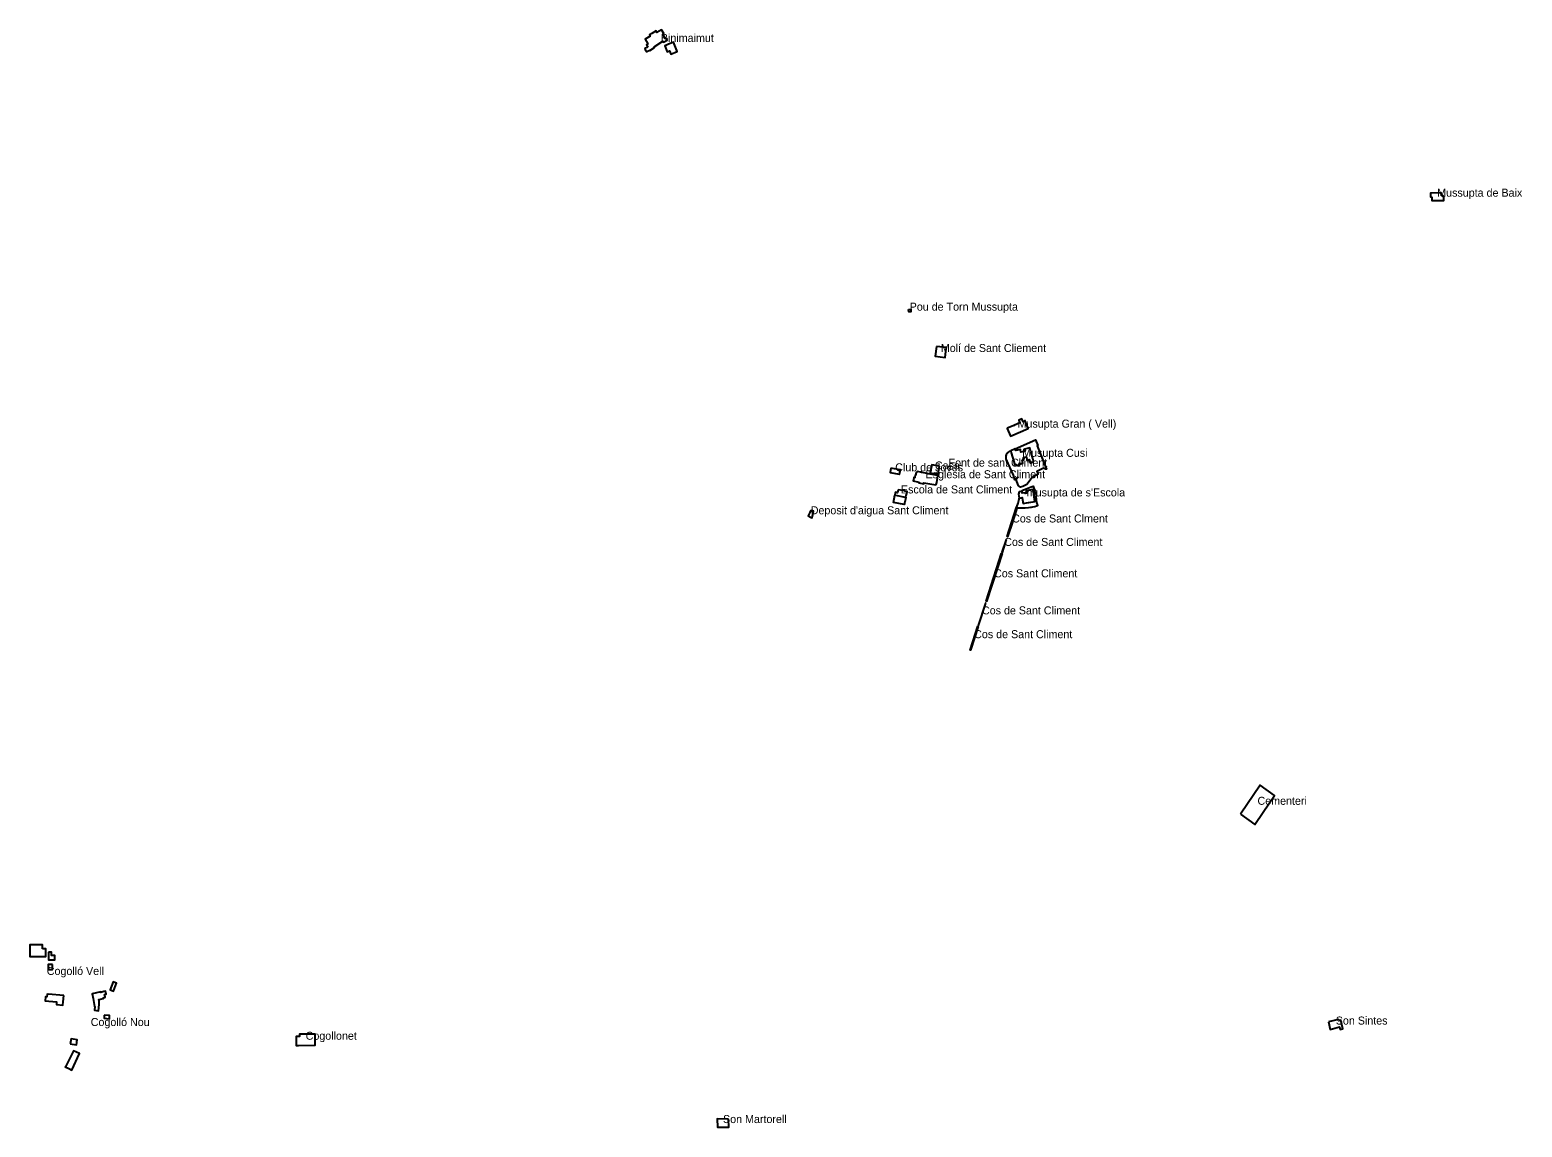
# Model space of a CAD drawing. Extents: x 599451 to 612034, y 4411179 to 4428219.
# Drawn here: x 601945 to 604183, y 4413252 to 4414898 of the extents above; entities that cross this region are included whole.
import ezdxf

# ---------------------------------------------------------------- set-up
doc = ezdxf.new("R2010")
doc.units = 0
for name, color, linetype in [('1', 7, 'Continuous'), ('Bé Arquitectònic', 7, 'Continuous'), ('Elememnts patrimonials', 7, 'Continuous'), ('Elements patrimonials', 7, 'Continuous')]:
    doc.layers.add(name, color=color, linetype=linetype)

msp = doc.modelspace()

# ---------------------------------------------------------------- linework, layer by layer
at = {"layer": '1'}
for points in [[(603262.3, 4414478.5), (603265.8, 4414478.8), (603266.1, 4414475.1), (603262.7, 4414474.8)], [(603322, 4414243.2), (603323.1, 4414243), (603323, 4414242.3), (603321.9, 4414242.5)], [(603424.1, 4414180.3), (603425.1, 4414180.5), (603422.4, 4414172.1), (603418.5, 4414160.1), (603418.3, 4414159.4), (603411.1, 4414137.6), (603410.5, 4414137.8)], [(603409.5, 4414133.3), (603408.8, 4414133.5), (603402.6, 4414114.3), (603403.2, 4414114.1)], [(603402.1, 4414112.8), (603402.7, 4414112.6), (603396.3, 4414092.7), (603379.4, 4414040.6), (603378.7, 4414040.8)], [(603378.4, 4414037.7), (603377.8, 4414037.9), (603366.8, 4414004.6), (603367.5, 4414004.3)], [(603366.4, 4414003.3), (603367.1, 4414003.1), (603355.4, 4413967.6), (603354.7, 4413967.4)]]:
    msp.add_lwpolyline(points, close=True, dxfattribs=at)
at = {"layer": 'Bé Arquitectònic'}
for points in [[(602871.5, 4414872.3), (602866.9, 4414869.9), (602866.8, 4414869.8), (602867.3, 4414868.8), (602868.7, 4414866.2), (602868.9, 4414865.8), (602869.3, 4414865), (602870, 4414865.4), (602874.4, 4414867.7), (602874.7, 4414867.3), (602881.5, 4414871.6), (602880.8, 4414872.7), (602894.1, 4414881.1), (602895.2, 4414879.4), (602900.6, 4414882.7), (602900.3, 4414883.5), (602899.6, 4414885.3), (602898.2, 4414884.5), (602894.1, 4414891.9), (602895.3, 4414892.5), (602892.2, 4414898.2), (602885.2, 4414894.3), (602884, 4414896.2), (602883.8, 4414896.6), (602877.7, 4414892.8), (602874.2, 4414890.5), (602875.2, 4414888.6), (602867.3, 4414884.3), (602871.6, 4414876.9), (602869.4, 4414875.6)], [(602900.7, 4414875.7), (602896.9, 4414874.2), (602900.4, 4414865.3), (602904.2, 4414866.7), (602906.1, 4414861.8), (602915.5, 4414865.5), (602914.8, 4414867.3), (602910.1, 4414879.4), (602901.6, 4414876.1)], [(604061.5, 4414649.2), (604061.3, 4414653.7), (604046.3, 4414653.2), (604045.4, 4414653.1), (604045.3, 4414647.4), (604047.4, 4414647.3), (604047.2, 4414641.9), (604061.2, 4414642.2), (604061.9, 4414642.2), (604065.3, 4414641.9), (604065.3, 4414647.4), (604064.4, 4414647.7), (604064.4, 4414649.1)], [(603760.5, 4413721.5), (603782, 4413706), (603794.2, 4413724.2), (603811.1, 4413749.4), (603790, 4413764.8)], [(601963.9, 4413519.4), (601963.9, 4413525.2), (601944.8, 4413525.2), (601944.8, 4413508.1), (601944.8, 4413507.9), (601949.5, 4413507.9), (601959.2, 4413507.9), (601963.9, 4413507.9), (601968.6, 4413507.9), (601968.6, 4413519.4)], [(601972.6, 4413514.1), (601972.6, 4413502.6), (601982.3, 4413502.6), (601982.3, 4413509.5), (601977.5, 4413509.5), (601977.5, 4413514.1)], [(601979, 4413495.6), (601972.3, 4413495.6), (601972.3, 4413488.4), (601979, 4413488.4)], [(602067.9, 4413456.6), (602070.2, 4413455.8), (602074.6, 4413467.8), (602069.5, 4413469.6), (602066.2, 4413460.8), (602065.1, 4413457.6)], [(601995.6, 4413449.4), (601972.1, 4413451.4), (601972, 4413451), (601970.7, 4413451.1), (601970.3, 4413447.2), (601968.2, 4413447.3), (601967.7, 4413441.3), (601985, 4413439.9), (601984.6, 4413435.8), (601994.4, 4413435), (601994.8, 4413439.8)], [(602055.6, 4413455.1), (602051.3, 4413454), (602051.1, 4413454.7), (602038.2, 4413451.6), (602039.8, 4413444.8), (602041.6, 4413432.8), (602042.2, 4413432.8), (602041.5, 4413427.2), (602047.5, 4413426.5), (602048.7, 4413435.8), (602048.6, 4413440.8), (602048.3, 4413443.1), (602055, 4413444.7), (602054.7, 4413445.9), (602057.6, 4413446.6), (602057, 4413449.1), (602056.6, 4413450.8), (602059.2, 4413451.4), (602058.1, 4413455.7)], [(602056.2, 4413420), (602056.1, 4413415.1), (602064, 4413414.5), (602064.4, 4413419.5)], [(603892.5, 4413409.7), (603894.7, 4413398.5), (603905.3, 4413401.3), (603909, 4413402.2), (603909.8, 4413398.1), (603913.9, 4413399.3), (603911, 4413412.1), (603907.7, 4413411.3), (603907.3, 4413413.4)], [(602347.6, 4413387.8), (602344, 4413387.8), (602344.1, 4413374.4), (602347.7, 4413374.4), (602372.7, 4413374.7), (602372.6, 4413388.1), (602372.6, 4413391.4), (602352.9, 4413391.2), (602349.1, 4413391.2), (602349.2, 4413387.9)], [(602005.4, 4413376.8), (602014.7, 4413375.5), (602015.7, 4413382.9), (602006.7, 4413384.2)], [(602003, 4413339.6), (602007.7, 4413337.4), (602019.2, 4413362.2), (602010.2, 4413366.4), (601998, 4413342.5), (601997.7, 4413342.1)], [(602992.7, 4413263.8), (602975.6, 4413264.1), (602976.2, 4413251.8), (602993, 4413251.8)]]:
    msp.add_lwpolyline(points, close=True, dxfattribs=at)
at = {"layer": 'Elememnts patrimonials'}
msp.add_lwpolyline([(603423.2, 4414267), (603422.3, 4414269.4), (603452.7, 4414282.8), (603456.2, 4414274.5), (603455.5, 4414274.2), (603469.2, 4414238.8), (603467.9, 4414238.9), (603464.7, 4414240.4), (603455.1, 4414235.7), (603456.9, 4414231.4), (603448.1, 4414226.7), (603439.7, 4414216.2), (603433.8, 4414213.2), (603430.4, 4414211.9), (603429, 4414212.4), (603427.3, 4414214), (603425, 4414220.4), (603423.9, 4414224.2), (603426.8, 4414226.9), (603426.6, 4414227.7), (603421.7, 4414223), (603420, 4414230.1), (603409.6, 4414253.2), (603409.1, 4414254.7), (603409, 4414255.4), (603408.8, 4414256.9), (603408.9, 4414258.4), (603409, 4414259.2), (603409.3, 4414260.6), (603409.5, 4414261.2), (603410.4, 4414262.8), (603411.2, 4414263.7), (603412, 4414264.5), (603413, 4414265.2), (603414, 4414265.8), (603415.7, 4414266.6), (603416.6, 4414263.3), (603421.7, 4414245.5), (603423.8, 4414246.2), (603424.1, 4414245.1), (603424.1, 4414245.1), (603424.1, 4414245.1), (603427.8, 4414243.9), (603428.8, 4414248.3), (603429.2, 4414246.8), (603429.2, 4414246.8), (603429.3, 4414246.7), (603434, 4414248.2), (603433.1, 4414251.9), (603434.2, 4414252.2), (603433.8, 4414253.9), (603435.7, 4414254.3), (603435.1, 4414256.5), (603438.8, 4414257.6), (603440.5, 4414252.6), (603440.5, 4414252.6), (603440.5, 4414252.5), (603443.6, 4414253.5), (603445.1, 4414248.7), (603445.2, 4414248.2), (603445.2, 4414248.2), (603445.3, 4414248.1), (603449.9, 4414250.7), (603449.8, 4414250.7), (603450, 4414250.8), (603448.9, 4414255.1), (603447.4, 4414260.2), (603446, 4414265.2), (603444.3, 4414271), (603436.3, 4414268.9), (603437.2, 4414265.8), (603431, 4414264.5), (603430.3, 4414268.5), (603430.3, 4414268.5), (603430.3, 4414268.6)], close=True, dxfattribs=at)
at = {"layer": 'Elements patrimonials'}
for points in [[(603304.2, 4414423.2), (603302.4, 4414408.4), (603317.3, 4414406.4), (603318.6, 4414415.5), (603319.4, 4414421.6)], [(603410.2, 4414300.2), (603415.4, 4414288.4), (603441.8, 4414300.1), (603437.3, 4414311.3), (603434.2, 4414310), (603432.3, 4414314.3), (603427.8, 4414312.3), (603429.4, 4414308.5), (603421.5, 4414305.2), (603421.7, 4414304.8), (603410.6, 4414300.3)], [(603422.3, 4414269.5), (603415.7, 4414266.6), (603416.6, 4414263.3), (603421.7, 4414245.5), (603423.8, 4414246.2), (603424.1, 4414245.1), (603424.1, 4414245.1), (603427.7, 4414244), (603428.8, 4414248.3), (603429.2, 4414246.8), (603429.2, 4414246.8), (603434, 4414248.2), (603433.1, 4414251.9), (603434.2, 4414252.2), (603433.8, 4414253.9), (603435.6, 4414254.4), (603435.1, 4414256.5), (603435.1, 4414256.6), (603438.8, 4414257.7), (603438.8, 4414257.6), (603440.5, 4414252.6), (603440.5, 4414252.6), (603443.6, 4414253.6), (603443.6, 4414253.5), (603445.1, 4414248.7), (603445.2, 4414248.2), (603445.2, 4414248.2), (603449.8, 4414250.7), (603450, 4414250.8), (603448.9, 4414255.1), (603447.4, 4414260.2), (603446, 4414265.2), (603444.3, 4414271), (603436.3, 4414268.9), (603437.2, 4414265.8), (603431, 4414264.5), (603431, 4414264.5), (603430.3, 4414268.5), (603430.3, 4414268.6), (603423.2, 4414267)], [(603308.9, 4414243.5), (603297.3, 4414245.6), (603295, 4414233.7), (603306.8, 4414231.3)], [(603236, 4414240.3), (603234.9, 4414234), (603248.6, 4414231.4), (603249, 4414231.4), (603250.2, 4414237.8), (603247, 4414238.3)], [(603306.4, 4414229.1), (603306.4, 4414229.1), (603305.8, 4414229.5), (603292.3, 4414232.1), (603288.1, 4414232.9), (603281.9, 4414234), (603281.9, 4414234.4), (603280.5, 4414234.6), (603275.8, 4414235.5), (603273.8, 4414233.9), (603273.5, 4414231.7), (603273.9, 4414230.9), (603272.6, 4414230), (603271.9, 4414226.9), (603272.3, 4414226.3), (603270.5, 4414226.6), (603269.8, 4414222.8), (603269.5, 4414221.3), (603278, 4414219.6), (603277.8, 4414218.4), (603285.3, 4414216.9), (603285.6, 4414218.6), (603303.2, 4414215.3), (603303.3, 4414216.1), (603304.1, 4414215.9), (603304.7, 4414219.1)], [(603241.9, 4414200), (603245.2, 4414199.4), (603255.1, 4414197.4), (603255.2, 4414197.7), (603258.4, 4414197.1), (603258.3, 4414196.5), (603256.8, 4414189.3), (603256.1, 4414185.9), (603240, 4414189.2)], [(603246.9, 4414208.2), (603246.1, 4414203.7), (603242.9, 4414204.3), (603242.7, 4414203.3), (603242.5, 4414203.3), (603241.9, 4414200), (603245.2, 4414199.4), (603245.2, 4414199.4), (603255.1, 4414197.4), (603255.2, 4414197.7), (603258.4, 4414197.1), (603259.1, 4414200.3), (603259.3, 4414200.3), (603260.4, 4414205.6), (603256.9, 4414206.2), (603256.9, 4414206.4)], [(603448.7, 4414208.5), (603446.2, 4414207.9), (603439.4, 4414206.5), (603438.7, 4414206.4), (603439.5, 4414202.8), (603437.3, 4414202.5), (603437.3, 4414203.4), (603433.1, 4414202.8), (603432.7, 4414205.7), (603432.7, 4414205.7), (603432, 4414205.5), (603432.2, 4414206.3), (603432.8, 4414206.8), (603435, 4414207.8), (603436.3, 4414208.3), (603446.6, 4414212.5), (603449.2, 4414213.5), (603450.4, 4414210.7), (603452.8, 4414205.2), (603453.2, 4414203.2), (603454, 4414198.1), (603453.3, 4414198), (603454.6, 4414188.4), (603454.8, 4414188.4), (603455.4, 4414185.8), (603455.9, 4414184.5), (603456.1, 4414184), (603454.4, 4414183.5), (603451.9, 4414182.7), (603448.3, 4414181.9), (603446.2, 4414181.6), (603445.5, 4414181.5), (603442.3, 4414181.1), (603437.2, 4414180.7), (603433.7, 4414180.6), (603429.7, 4414180.5), (603425.1, 4414180.5), (603424.1, 4414180.3), (603425.5, 4414184.2), (603426.2, 4414186.3), (603426.8, 4414188.1), (603428, 4414192.2), (603428.5, 4414194.4), (603428.5, 4414195.4), (603432.9, 4414196.2), (603434.5, 4414187.7), (603439.3, 4414188.4), (603442.4, 4414189), (603452.1, 4414190.5), (603449.9, 4414204.8)], [(603432.7, 4414205.7), (603428.2, 4414204.9), (603427.4, 4414201.7), (603428.5, 4414195.5), (603432.9, 4414196.3), (603434.5, 4414187.7), (603439.3, 4414188.4), (603449.5, 4414190.1), (603452.1, 4414190.5), (603450.6, 4414201), (603449.9, 4414204.8), (603448.7, 4414208.5), (603446.2, 4414207.9), (603446.2, 4414207.9), (603439.4, 4414206.6), (603438.7, 4414206.5), (603439.4, 4414202.9), (603437.3, 4414202.5), (603437.3, 4414203.4), (603437.2, 4414203.4), (603433.1, 4414202.8), (603432.7, 4414205.7)], [(603114.6, 4414173.8), (603114.5, 4414173.9), (603111.8, 4414169.2), (603116.7, 4414166.5), (603117.8, 4414165.9), (603117.9, 4414166.5), (603119.1, 4414171.2), (603118.8, 4414171.3), (603119.8, 4414176.2), (603117.4, 4414176.8), (603115.9, 4414176.4)]]:
    msp.add_lwpolyline(points, close=True, dxfattribs=at)

# ---------------------------------------------------------------- texts
at = {"layer": '1'}
for s, p in [('Pou de Torn Mussupta', (603264.2, 4414476.8)), ('Font de sant Climent', (603322.5, 4414242.8)), ('Cos de Sant Clment', (603417.8, 4414159)), ('Cos de Sant Climent', (603406, 4414123.8)), ('Cos Sant Climent', (603390.7, 4414076.7)), ('Cos de Sant Climent', (603372.6, 4414021.1)), ('Cos de Sant Climent', (603360.9, 4413985.4))]:
    msp.add_text(s, height=12, dxfattribs=at).set_placement(p)
at = {"layer": 'Bé Arquitectònic'}
for s, p in [('Binimaimut', (602891.1, 4414880)), ('Mussupta de Baix', (604055.3, 4414647.8)), ('Cementeri', (603785.8, 4413735.4)), ('Cogolló Vell', (601970.2, 4413480.1)), ('Cogolló Nou', (602036.1, 4413403.5)), ('Son Sintes', (603903.2, 4413405.7)), ('Cogollonet', (602358.4, 4413382.9)), ('Son Martorell', (602984.3, 4413257.9))]:
    msp.add_text(s, height=12, dxfattribs=at).set_placement(p)
at = {"layer": 'Elements patrimonials'}
for s, p in [('Molí de Sant Cliement', (603310.9, 4414414.8)), ('Musupta Gran ( Vell)', (603426, 4414301.3)), ('Musupta Cusi', (603432.8, 4414257.5)), ('Club de Joves', (603242.5, 4414235.8)), ('Casa', (603302, 4414238.5)), ('Església de Sant Climent', (603288, 4414225.4)), ('Escola de Sant Climent', (603251.1, 4414202.6)), ("musupta de s'Escola", (603439.7, 4414198.1)), ("Deposit d'aigua Sant Climent", (603115.8, 4414171.3))]:
    msp.add_text(s, height=12, dxfattribs=at).set_placement(p)

doc.saveas('drawing.dxf')
